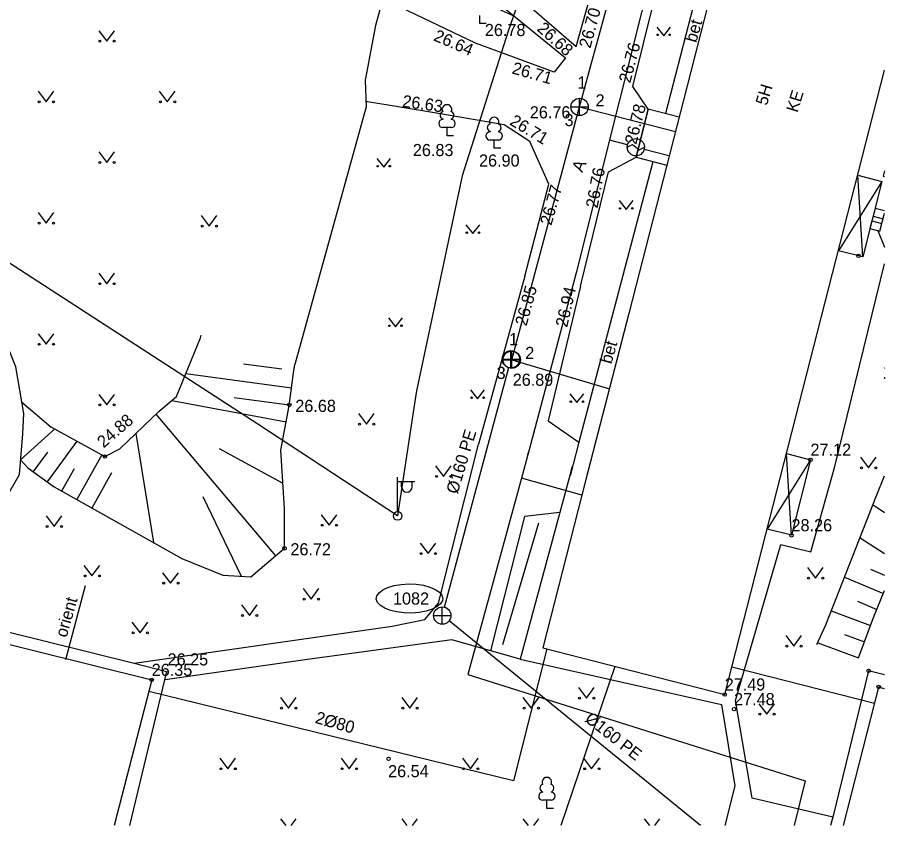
# Model space of a CAD drawing. Extents: x 714391 to 714584, y 6589993 to 6590151.
# Drawn here: x 714533.8 to 714583.9, y 6589992.7 to 6590039.4 of the extents above; entities that cross this region are included whole.
import ezdxf

# ---------------------------------------------------------------- set-up
doc = ezdxf.new("R2010")
doc.units = 0
for name, color, linetype in [('HALJASTUS', 7, 'Continuous'), ('HOONE', 7, 'Continuous'), ('HOONEDET', 7, 'Continuous'), ('KAEVU_NR', 7, 'Continuous'), ('KKAEV', 7, 'Continuous'), ('KORGUS', 7, 'Continuous'), ('KTRASS', 7, 'Continuous'), ('MPKAABEL', 7, 'Continuous'), ('POST', 7, 'Continuous'), ('PUU', 7, 'Continuous'), ('RELJEEF', 7, 'Continuous'), ('SITRASS', 7, 'Continuous'), ('TEE', 7, 'Continuous'), ('TORU NR', 7, 'Continuous'), ('TTRASS', 7, 'Continuous')]:
    doc.layers.add(name, color=color, linetype=linetype)

msp = doc.modelspace()

# ---------------------------------------------------------------- linework, layer by layer
at = {"layer": 'HALJASTUS'}
for p, q in [((714538.537, 6590038.607), (714539, 6590038)), ((714539, 6590038), (714539.446, 6590038.607)), ((714570.761, 6590038.818), (714571.166, 6590038.313)), ((714571.166, 6590038.313), (714571.561, 6590038.818)), ((714535.037, 6590035.107), (714535.5, 6590034.5)), ((714535.5, 6590034.5), (714535.946, 6590035.107)), ((714542.037, 6590035.107), (714542.5, 6590034.5)), ((714542.5, 6590034.5), (714542.946, 6590035.107)), ((714538.537, 6590031.607), (714539, 6590031)), ((714539, 6590031), (714539.446, 6590031.607)), ((714554.596, 6590031.232), (714555.001, 6590030.727)), ((714555.001, 6590030.727), (714555.396, 6590031.232)), ((714568.593, 6590028.793), (714568.998, 6590028.288)), ((714568.998, 6590028.288), (714569.393, 6590028.793)), ((714535.037, 6590028.107), (714535.5, 6590027.5)), ((714535.5, 6590027.5), (714535.946, 6590028.107)), ((714544.458, 6590027.932), (714544.921, 6590027.325)), ((714544.921, 6590027.325), (714545.367, 6590027.932)), ((714559.743, 6590027.394), (714560.148, 6590026.889)), ((714560.148, 6590026.889), (714560.543, 6590027.394)), ((714538.537, 6590024.607), (714539, 6590024)), ((714539, 6590024), (714539.446, 6590024.607)), ((714555.273, 6590022.02), (714555.678, 6590021.515)), ((714555.678, 6590021.515), (714556.073, 6590022.02)), ((714535.037, 6590021.107), (714535.5, 6590020.5)), ((714535.5, 6590020.5), (714535.946, 6590021.107)), ((714583.889, 6590019.156), (714583.92, 6590019.114)), ((714538.537, 6590017.607), (714539, 6590017)), ((714539, 6590017), (714539.446, 6590017.607)), ((714560.014, 6590017.866), (714560.419, 6590017.361)), ((714560.419, 6590017.361), (714560.814, 6590017.866)), ((714565.749, 6590017.641), (714566.154, 6590017.136)), ((714566.154, 6590017.136), (714566.549, 6590017.641)), ((714553.53, 6590016.5), (714553.993, 6590015.893)), ((714553.993, 6590015.893), (714554.439, 6590016.5)), ((714582.516, 6590013.977), (714582.979, 6590013.37)), ((714582.979, 6590013.37), (714583.425, 6590013.977)), ((714557.983, 6590013.483), (714558.446, 6590012.876)), ((714558.446, 6590012.876), (714558.892, 6590013.483)), ((714535.499, 6590010.591), (714535.962, 6590009.984)), ((714535.962, 6590009.984), (714536.408, 6590010.591)), ((714551.387, 6590010.657), (714551.85, 6590010.05)), ((714551.85, 6590010.05), (714552.296, 6590010.657)), ((714557.091, 6590009.021), (714557.554, 6590008.414)), ((714557.554, 6590008.414), (714558, 6590009.021)), ((714537.686, 6590007.732), (714538.149, 6590007.125)), ((714538.149, 6590007.125), (714538.595, 6590007.732)), ((714579.457, 6590007.611), (714579.92, 6590007.004)), ((714579.92, 6590007.004), (714580.366, 6590007.611)), ((714542.228, 6590007.311), (714542.691, 6590006.704)), ((714542.691, 6590006.704), (714543.137, 6590007.311)), ((714550.346, 6590006.393), (714550.809, 6590005.786)), ((714550.809, 6590005.786), (714551.255, 6590006.393)), ((714546.775, 6590005.451), (714547.238, 6590004.844)), ((714547.238, 6590004.844), (714547.684, 6590005.451)), ((714540.461, 6590004.453), (714540.924, 6590003.846)), ((714540.924, 6590003.846), (714541.37, 6590004.453)), ((714578.208, 6590003.68), (714578.671, 6590003.073)), ((714578.671, 6590003.073), (714579.117, 6590003.68)), ((714566.244, 6590000.679), (714566.707, 6590000.072)), ((714566.707, 6590000.072), (714567.153, 6590000.679)), ((714549.037, 6590000.107), (714549.5, 6589999.5)), ((714549.5, 6589999.5), (714549.946, 6590000.107)), ((714556.037, 6590000.107), (714556.5, 6589999.5)), ((714556.5, 6589999.5), (714556.946, 6590000.107)), ((714563.037, 6590000.107), (714563.5, 6589999.5)), ((714563.5, 6589999.5), (714563.946, 6590000.107)), ((714576.648, 6589999.748), (714577.111, 6589999.141)), ((714577.111, 6589999.141), (714577.557, 6589999.748)), ((714545.537, 6589996.607), (714546, 6589996)), ((714546, 6589996), (714546.446, 6589996.607)), ((714552.537, 6589996.607), (714553, 6589996)), ((714553, 6589996), (714553.446, 6589996.607)), ((714559.537, 6589996.607), (714560, 6589996)), ((714560, 6589996), (714560.446, 6589996.607)), ((714566.537, 6589996.607), (714567, 6589996)), ((714567, 6589996), (714567.446, 6589996.607)), ((714549.037, 6589993.107), (714549.339, 6589992.711)), ((714549.655, 6589992.711), (714549.946, 6589993.107)), ((714556.037, 6589993.107), (714556.339, 6589992.711)), ((714556.655, 6589992.711), (714556.946, 6589993.107)), ((714563.037, 6589993.107), (714563.339, 6589992.711)), ((714563.655, 6589992.711), (714563.946, 6589993.107)), ((714570.037, 6589993.107), (714570.339, 6589992.711)), ((714570.655, 6589992.711), (714570.946, 6589993.107))]:
    msp.add_line(p, q, dxfattribs=at)
msp.add_lwpolyline([(714563.928, 6590010.174), (714561.85, 6590003.147)], dxfattribs=at)
for centre, radius in [((714538.599, 6590038), 0.055), ((714539.428, 6590038), 0.055), ((714570.813, 6590038.368), 0.0428), ((714571.513, 6590038.368), 0.0452), ((714535.099, 6590034.5), 0.055), ((714535.928, 6590034.5), 0.055), ((714542.099, 6590034.5), 0.055), ((714542.928, 6590034.5), 0.055), ((714538.599, 6590031), 0.055), ((714539.428, 6590031), 0.055), ((714554.648, 6590030.782), 0.0428), ((714555.348, 6590030.782), 0.0452), ((714568.645, 6590028.344), 0.0428), ((714569.345, 6590028.344), 0.0452), ((714535.099, 6590027.5), 0.055), ((714535.928, 6590027.5), 0.055), ((714544.52, 6590027.325), 0.055), ((714545.349, 6590027.325), 0.055), ((714559.795, 6590026.944), 0.0428), ((714560.495, 6590026.944), 0.0452), ((714538.599, 6590024), 0.055), ((714539.428, 6590024), 0.055), ((714555.325, 6590021.571), 0.0428), ((714556.025, 6590021.571), 0.0452), ((714535.099, 6590020.5), 0.055), ((714535.928, 6590020.5), 0.055), ((714560.066, 6590017.417), 0.0428), ((714560.766, 6590017.417), 0.0452), ((714538.599, 6590017), 0.055), ((714539.428, 6590017), 0.055), ((714565.801, 6590017.191), 0.0428), ((714566.501, 6590017.191), 0.0452), ((714553.592, 6590015.893), 0.055), ((714554.421, 6590015.893), 0.055), ((714582.578, 6590013.37), 0.055), ((714583.407, 6590013.37), 0.055), ((714558.045, 6590012.876), 0.055), ((714558.874, 6590012.876), 0.055), ((714535.561, 6590009.984), 0.055), ((714536.39, 6590009.984), 0.055), ((714551.449, 6590010.05), 0.055), ((714552.278, 6590010.05), 0.055), ((714557.153, 6590008.414), 0.055), ((714557.982, 6590008.414), 0.055), ((714537.748, 6590007.125), 0.055), ((714538.577, 6590007.125), 0.055), ((714579.519, 6590007.004), 0.055), ((714580.348, 6590007.004), 0.055), ((714542.29, 6590006.704), 0.055), ((714543.119, 6590006.704), 0.055), ((714550.408, 6590005.786), 0.055), ((714551.237, 6590005.786), 0.055), ((714546.837, 6590004.844), 0.055), ((714547.666, 6590004.844), 0.055), ((714540.523, 6590003.846), 0.055), ((714541.352, 6590003.846), 0.055), ((714578.27, 6590003.073), 0.055), ((714579.099, 6590003.073), 0.055), ((714566.306, 6590000.072), 0.055), ((714567.135, 6590000.072), 0.055), ((714549.099, 6589999.5), 0.055), ((714549.928, 6589999.5), 0.055), ((714556.099, 6589999.5), 0.055), ((714556.928, 6589999.5), 0.055), ((714563.099, 6589999.5), 0.055), ((714563.928, 6589999.5), 0.055), ((714576.71, 6589999.141), 0.055), ((714577.539, 6589999.141), 0.055), ((714545.599, 6589996), 0.055), ((714546.428, 6589996), 0.055), ((714552.599, 6589996), 0.055), ((714553.428, 6589996), 0.055), ((714559.599, 6589996), 0.055), ((714560.428, 6589996), 0.055), ((714566.599, 6589996), 0.055), ((714567.428, 6589996), 0.055)]:
    msp.add_circle(centre, radius, dxfattribs=at)
msp.add_arc((714583.951, 6590018.549), 0.055, 123.9567, 236.0433, dxfattribs=at)
at = {"layer": 'HOONE'}
for p, q in [((714569.071, 6590032.009), (714568.027, 6590032.289)), ((714569.054, 6590031.879), (714569.354, 6590032.029)), ((714569.354, 6590032.029), (714569.754, 6590031.729)), ((714569.754, 6590031.729), (714570.054, 6590031.879)), ((714570.039, 6590031.758), (714571.46, 6590031.402))]:
    msp.add_line(p, q, dxfattribs=at)
for points in [[(714564.262, 6590078.768), (714578.616, 6590074.926), (714573.649, 6590054.703), (714566.105, 6590024.628), (714563.31, 6590014.121), (714563.349, 6590014.272), (714562.951, 6590012.774), (714559.846, 6590001.436), (714579.323, 6589995.303), (714578.688, 6589992.711)], [(714583.92, 6590060.605), (714579.267, 6590061.805), (714569.151, 6590022.283), (714566.669, 6590012.701), (714564.179, 6590002.982), (714564.176, 6590002.972), (714574.684, 6590000.28), (714583.92, 6590036.33)], [(714572.058, 6590033.612), (714570.266, 6590034.075), (714569.565, 6590031.31), (714571.34, 6590030.843)], [(714582.364, 6590030.256), (714583.754, 6590029.9), (714582.66, 6590025.541), (714581.249, 6590025.903)], [(714582.66, 6590025.541), (714582.364, 6590030.256)], [(714583.754, 6590029.9), (714581.249, 6590025.903)], [(714563.349, 6590014.272), (714563.31, 6590014.121)], [(714578.248, 6590014.189), (714579.637, 6590013.833), (714578.543, 6590009.474), (714577.132, 6590009.835)], [(714578.543, 6590009.474), (714578.248, 6590014.189)], [(714579.637, 6590013.833), (714577.132, 6590009.835)], [(714566.434, 6590011.783), (714562.951, 6590012.774)], [(714528.305, 6589992.711), (714531.142, 6590003.734), (714541.598, 6590001.124)], [(714541.598, 6590001.124), (714539.44, 6589992.711)], [(714583.92, 6590000.611), (714583.566, 6590000.701), (714581.521, 6589992.711)]]:
    msp.add_lwpolyline(points, dxfattribs=at)
msp.add_circle((714569.554, 6590031.879), 0.5, dxfattribs=at)
at = {"layer": 'HOONEDET'}
msp.add_line((714569.565, 6590031.31), (714570.266, 6590034.075), dxfattribs=at)
for points in [[(714527.976, 6589995.097), (714530.413, 6590004.606), (714540.577, 6590002.096), (714542.446, 6590001.618), (714540.308, 6589992.711)], [(714583.92, 6590001.414), (714582.992, 6590001.65), (714580.929, 6589993.204), (714580.799, 6589992.711)]]:
    msp.add_lwpolyline(points, dxfattribs=at)
at = {"layer": 'KAEVU_NR'}
msp.add_lwpolyline([(714558.405, 6590005.824), (714558.387, 6590005.71), (714558.387, 6590005.71), (714558.279, 6590005.525), (714558.279, 6590005.525), (714558.079, 6590005.355), (714558.079, 6590005.355), (714557.796, 6590005.21), (714557.796, 6590005.21), (714557.445, 6590005.097), (714557.445, 6590005.097), (714557.045, 6590005.021), (714557.045, 6590005.021), (714556.616, 6590004.986), (714556.616, 6590004.986), (714556.181, 6590004.995), (714556.181, 6590004.995), (714555.761, 6590005.046), (714555.761, 6590005.046), (714555.378, 6590005.138), (714555.378, 6590005.138), (714555.053, 6590005.265), (714555.053, 6590005.265), (714554.801, 6590005.421), (714554.801, 6590005.421), (714554.636, 6590005.597), (714554.636, 6590005.597), (714554.567, 6590005.786), (714554.567, 6590005.786), (714554.597, 6590005.976), (714554.597, 6590005.976), (714554.724, 6590006.159), (714554.724, 6590006.159), (714554.942, 6590006.324), (714554.942, 6590006.324), (714555.24, 6590006.463), (714555.24, 6590006.463), (714555.602, 6590006.57), (714555.602, 6590006.57), (714556.009, 6590006.638), (714556.009, 6590006.638), (714556.442, 6590006.664), (714556.442, 6590006.664), (714556.876, 6590006.646), (714556.876, 6590006.646), (714557.29, 6590006.587), (714557.29, 6590006.587), (714557.663, 6590006.488), (714557.663, 6590006.488), (714557.975, 6590006.354), (714557.975, 6590006.354), (714558.21, 6590006.193), (714558.21, 6590006.193), (714558.356, 6590006.014), (714558.356, 6590006.014), (714558.405, 6590005.824), (714558.405, 6590005.824)], dxfattribs=at)
at = {"layer": 'KKAEV'}
for p, q in [((714566.306, 6590033.702), (714566.306, 6590034.702)), ((714565.806, 6590034.202), (714566.806, 6590034.202)), ((714562.34, 6590019.14), (714562.34, 6590020.14)), ((714562.392, 6590019.109), (714562.392, 6590020.109)), ((714561.84, 6590019.64), (714562.84, 6590019.64)), ((714561.892, 6590019.609), (714562.892, 6590019.609)), ((714558.378, 6590004.342), (714558.378, 6590005.342)), ((714557.878, 6590004.842), (714558.878, 6590004.842))]:
    msp.add_line(p, q, dxfattribs=at)
for centre in [(714566.306, 6590034.202), (714562.34, 6590019.64), (714562.392, 6590019.609), (714558.378, 6590004.842)]:
    msp.add_circle(centre, 0.5, dxfattribs=at)
at = {"layer": 'KORGUS'}
for centre in [(714582.411, 6590025.605), (714549.547, 6590017.002), (714538.897, 6590014.023), (714579.637, 6590013.833), (714578.543, 6590009.474), (714549.264, 6590008.722), (714582.992, 6590001.65), (714541.598, 6590001.124), (714574.684, 6590000.28), (714583.571, 6590000.719), (714575.227, 6589999.433), (714555.277, 6589996.567)]:
    msp.add_circle(centre, 0.1, dxfattribs=at)
at = {"layer": 'KTRASS'}
for p, q in [((714566.306, 6590034.202), (714571.457, 6590053.19)), ((714562.392, 6590019.609), (714566.306, 6590034.202)), ((714566.306, 6590034.202), (714571.84, 6590032.789)), ((714562.392, 6590019.609), (714568.025, 6590017.935))]:
    msp.add_line(p, q, dxfattribs=at)
for points in [[(714558.507, 6590005.325), (714562.211, 6590019.157)], [(714573.285, 6589992.711), (714558.766, 6590004.526)]]:
    msp.add_lwpolyline(points, dxfattribs=at)
at = {"layer": 'MPKAABEL'}
for points in [[(714565.296, 6590047.518), (714562.179, 6590038.578), (714559.533, 6590030.225), (714556.889, 6590017.808), (714556.781, 6590017.088), (714556.359, 6590014.294), (714555.801, 6590010.589), (714547.733, 6590015.896), (714531.176, 6590026.61), (714500.538, 6590019.577)], [(714583.501, 6590027.101), (714583.92, 6590026.1)]]:
    msp.add_lwpolyline(points, dxfattribs=at)
at = {"layer": 'POST'}
for p, q in [((714583.373, 6590028.343), (714583.064, 6590027.189)), ((714583.92, 6590028.197), (714583.373, 6590028.343)), ((714583.641, 6590027.035), (714583.92, 6590028.079)), ((714583.184, 6590027.635), (714583.76, 6590027.481)), ((714583.254, 6590027.897), (714583.83, 6590027.743)), ((714583.064, 6590027.189), (714583.641, 6590027.035)), ((714555.801, 6590010.839), (714555.801, 6590012.839)), ((714555.801, 6590012.589), (714556.801, 6590012.589)), ((714556.028, 6590012.268), (714556.028, 6590012.589)), ((714556.64, 6590012.268), (714556.64, 6590012.589))]:
    msp.add_line(p, q, dxfattribs=at)
msp.add_circle((714555.801, 6590010.589), 0.25, dxfattribs=at)
msp.add_arc((714556.334, 6590012.268), 0.306, 180, 0, dxfattribs=at)
at = {"layer": 'PUU'}
for p, q in [((714560.539, 6590039.015), (714560.539, 6590039.49)), ((714560.919, 6590039.015), (714560.539, 6590039.015)), ((714558.41, 6590033.516), (714558.41, 6590033.486)), ((714558.89, 6590033.516), (714558.89, 6590033.486)), ((714558.89, 6590033.011), (714558.41, 6590033.011)), ((714558.65, 6590032.536), (714558.65, 6590033.011)), ((714559.03, 6590032.536), (714558.65, 6590032.536)), ((714561.135, 6590032.799), (714561.135, 6590032.769)), ((714561.615, 6590032.799), (714561.615, 6590032.769)), ((714561.615, 6590032.294), (714561.135, 6590032.294)), ((714561.375, 6590031.819), (714561.375, 6590032.294)), ((714561.755, 6590031.819), (714561.375, 6590031.819)), ((714564.658, 6589994.175), (714564.178, 6589994.175)), ((714564.418, 6589993.7), (714564.418, 6589994.175)), ((714564.798, 6589993.7), (714564.418, 6589993.7))]:
    msp.add_line(p, q, dxfattribs=at)
for centre, radius, start, end in [((714558.65, 6590034.056), 0.277, 332.5799, 207.4201), ((714558.412, 6590033.249), 0.237, 90, 270), ((714558.46, 6590033.724), 0.212, 105.2441, 257.079), ((714558.887, 6590033.249), 0.237, 270, 90), ((714558.84, 6590033.724), 0.212, 282.921, 74.7559), ((714561.375, 6590033.339), 0.277, 332.5799, 207.4201), ((714561.185, 6590033.007), 0.212, 105.2441, 257.079), ((714561.565, 6590033.007), 0.212, 282.921, 74.7559), ((714561.137, 6590032.531), 0.237, 90, 270), ((714561.612, 6590032.531), 0.237, 270, 90), ((714564.418, 6589995.22), 0.277, 332.5799, 207.4201), ((714564.248, 6589994.873), 0.233, 109.0217, 253.1415), ((714564.588, 6589994.873), 0.233, 286.8508, 70.9859), ((714564.181, 6589994.412), 0.238, 90.0016, 269.3953), ((714564.655, 6589994.412), 0.238, 270.6047, 89.9984)]:
    msp.add_arc(centre, radius, start, end, dxfattribs=at)
at = {"layer": 'RELJEEF'}
for points in [[(714562.558, 6590039.424), (714560.262, 6590040.479), (714558.242, 6590041.236), (714555.943, 6590041.488), (714554.821, 6590040.031), (714554.512, 6590038.91), (714553.923, 6590035.744), (714553.979, 6590034.203), (714549.861, 6590019.341)], [(714534.101, 6590017.166), (714535.781, 6590015.731), (714538.897, 6590014.023), (714539.751, 6590014.475), (714542.028, 6590016.64), (714543.038, 6590017.493), (714544.414, 6590020.871), (714544.452, 6590021.028)], [(714534.03, 6590013.833), (714534.442, 6590013.377), (714535.963, 6590012.263), (714543.34, 6590008.142), (714545.701, 6590007.171), (714547.329, 6590007.084), (714549.264, 6590008.722), (714549.264, 6590011.02), (714549.058, 6590014.381), (714549.538, 6590016.953), (714549.795, 6590018.85), (714549.861, 6590019.341)], [(714546.89, 6590019.379), (714549.118, 6590019.079)], [(714543.578, 6590018.818), (714549.679, 6590017.994)], [(714546.367, 6590017.432), (714549.545, 6590017.003)], [(714542.755, 6590017.254), (714549.364, 6590016.019)], [(714541.838, 6590016.46), (714548.754, 6590008.29)], [(714535.998, 6590015.612), (714534.03, 6590013.833)], [(714537.281, 6590014.909), (714535.56, 6590012.558)], [(714540.675, 6590015.354), (714541.709, 6590009.053)], [(714545.486, 6590014.485), (714549.174, 6590012.481)], [(714535.575, 6590014.271), (714534.753, 6590013.149)], [(714538.719, 6590014.12), (714537.273, 6590011.531)], [(714537.121, 6590013.31), (714536.4, 6590012.019)], [(714539.281, 6590013.075), (714538.146, 6590011.043)], [(714580.012, 6590003.167), (714580.52, 6590004.309), (714583.438, 6590011.708), (714583.92, 6590012.913)], [(714544.551, 6590011.707), (714546.764, 6590007.114)], [(714583.248, 6590011.225), (714583.92, 6590010.794)], [(714582.5, 6590009.329), (714583.92, 6590008.419)], [(714583.106, 6590007.516), (714583.92, 6590007.176)], [(714581.605, 6590007.06), (714583.854, 6590006.119)], [(714582.405, 6590002.392), (714583.272, 6590004.728), (714583.92, 6590006.279)], [(714582.353, 6590005.663), (714583.468, 6590005.197)], [(714580.835, 6590005.108), (714583.101, 6590004.267)], [(714581.607, 6590003.754), (714582.753, 6590003.329)], [(714580.055, 6590003.264), (714582.405, 6590002.392)]]:
    msp.add_lwpolyline(points, dxfattribs=at)
at = {"layer": 'SITRASS'}
msp.add_line((714536.636, 6590002.309), (714537.77, 6590006.584), dxfattribs=at)
msp.add_lwpolyline([(714568.333, 6590001.907), (714565.216, 6589992.711)], dxfattribs=at)
at = {"layer": 'TEE'}
for p, q in [((714575.561, 6590050.401), (714571.262, 6590033.816)), ((714563.14, 6590024.436), (714560.476, 6590014.732))]:
    msp.add_line(p, q, dxfattribs=at)
for points in [[(714523.83, 6590060.323), (714524.838, 6590059.346), (714527.207, 6590057.322), (714530.612, 6590055.143), (714533.466, 6590053.803), (714539.862, 6590051.373), (714544.939, 6590049.949), (714549.327, 6590048.405), (714554.662, 6590046.175), (714555.973, 6590045.43), (714557.565, 6590044.068), (714560.558, 6590042.157), (714562.991, 6590040.414), (714566.112, 6590037.695), (714570.003, 6590051.519), (714571.762, 6590062.449)], [(714530.594, 6590004.671), (714529.575, 6590005.355), (714533.957, 6590012.977), (714534.157, 6590015.322), (714534.216, 6590016.497), (714533.749, 6590019.201), (714531.843, 6590023.902), (714529.246, 6590029.211), (714527.989, 6590032.696), (714528.19, 6590034.745), (714530.462, 6590043.175), (714532.838, 6590052.177), (714538.719, 6590050.416), (714545.918, 6590048.286), (714551.944, 6590046.002), (714557.184, 6590043.351), (714560.131, 6590041.46), (714562.296, 6590039.644), (714565.486, 6590037.034), (714564.832, 6590036.22), (714560.292, 6590037.889), (714555.09, 6590040.381)], [(714570.266, 6590034.075), (714569.384, 6590035.393), (714573.093, 6590050.376), (714574.585, 6590050.689)], [(714563.14, 6590024.436), (714564.533, 6590029.748), (714563.424, 6590032.21), (714561.942, 6590033.166), (714558.167, 6590033.821), (714553.968, 6590034.517)], [(714570.544, 6590031.044), (714566.254, 6590014.851), (714565.753, 6590012.916), (714565.868, 6590013.421), (714562.875, 6590002.32), (714574.49, 6589999.706), (714575.278, 6589995.019), (714574.698, 6589992.711)], [(714566.355, 6590023.857), (714567.966, 6590030.449), (714569.565, 6590031.31)], [(714583.92, 6590030.513), (714583.839, 6590030.215), (714583.92, 6590030.195)], [(714575.316, 6589999.931), (714577.926, 6590008.933), (714579.657, 6590008.519), (714581.036, 6590013.442), (714583.92, 6590025.141)], [(714566.355, 6590023.857), (714564.497, 6590016.082), (714566.254, 6590014.851)], [(714540.577, 6590002.096), (714555.48, 6590004.225), (714557.374, 6590004.62), (714558.154, 6590005.561), (714560.476, 6590014.732)], [(714565.161, 6590010.798), (714563.123, 6590010.552), (714561.168, 6590002.803)], [(714562.875, 6590002.32), (714558.922, 6590003.44), (714550.46, 6590002.28), (714542.369, 6590001.127)], [(714580.929, 6589993.204), (714576.272, 6589994.305), (714575.316, 6589999.931)]]:
    msp.add_lwpolyline(points, dxfattribs=at)
at = {"layer": 'TTRASS'}
for points in [[(714564.418, 6590002.91), (714562.493, 6589995.291), (714541.427, 6590000.461)], [(714583.329, 6589999.77), (714575.087, 6590001.854)]]:
    msp.add_lwpolyline(points, dxfattribs=at)

# ---------------------------------------------------------------- texts
at = {"layer": 'HOONE'}
for s, p in [('5H', (714577.118, 6590034.244)), ('KE', (714578.887, 6590033.843))]:
    msp.add_text(s, height=0.7, rotation=73.0726, dxfattribs=at).set_placement(p)
at = {"layer": 'HOONEDET'}
for p in [(714573.041, 6590037.878), (714568.144, 6590019.327)]:
    msp.add_text('bet', height=0.7, rotation=74.1412, dxfattribs=at).set_placement(p)
at = {"layer": 'KAEVU_NR'}
msp.add_text('1082', height=0.7, dxfattribs=at).set_placement((714555.531, 6590005.474))
at = {"layer": 'KORGUS'}
for s, rotation, p in [('26.70', 74.9315, (714566.928, 6590037.554)), ('26.68', 317.8755, (714563.801, 6590038.657)), ('26.64', 336.7099, (714557.826, 6590038.06)), ('26.76', 75.2218, (714569.229, 6590035.547)), ('26.71', 344.1025, (714562.355, 6590036.147)), ('26.63', 352.0992, (714556.038, 6590034.211)), ('26.78', 75.9638, (714569.574, 6590031.998)), ('26.71', 328.9729, (714562.217, 6590033.21)), ('26.76', 79.0278, (714567.336, 6590028.327)), ('26.77', 74.1128, (714564.674, 6590027.325)), ('26.85', 74.71, (714563.24, 6590021.518)), ('26.94', 77.125, (714565.586, 6590021.445)), ('24.88', 40.7277, (714538.823, 6590014.483))]:
    msp.add_text(s, height=0.7, rotation=rotation, dxfattribs=at).set_placement(p)
for s, p in [('26.78', (714560.837, 6590038.297)), ('26.76', (714563.431, 6590033.544)), ('26.83', (714556.679, 6590031.366)), ('26.90', (714560.499, 6590030.762)), ('26.89', (714562.443, 6590018.106)), ('26.68', (714549.891, 6590016.597)), ('27.12', (714579.637, 6590014.066)), ('28.26', (714578.543, 6590009.707)), ('26.72', (714549.607, 6590008.317)), ('26.25', (714542.516, 6590001.96)), ('26.35', (714541.598, 6590001.357)), ('27.49', (714574.684, 6590000.513)), ('27.48', (714575.227, 6589999.666)), ('26.54', (714555.249, 6589995.507))]:
    msp.add_text(s, height=0.7, dxfattribs=at).set_placement(p)
at = {"layer": 'KTRASS'}
for rotation, p in [(73.128, (714559.254, 6590011.814)), (321.8247, (714566.56, 6589998.775))]:
    msp.add_text('%%c160 PE', height=0.7, rotation=rotation, dxfattribs=at).set_placement(p)
at = {"layer": 'SITRASS'}
msp.add_text('orient', height=0.7, rotation=73.9626, dxfattribs=at).set_placement((714536.679, 6590003.534))
at = {"layer": 'TEE'}
msp.add_text('A', height=0.7, rotation=67.1355, dxfattribs=at).set_placement((714566.464, 6590030.386))
at = {"layer": 'TORU NR'}
for s, p in [('1', (714566.184, 6590035.267)), ('2', (714567.229, 6590034.232)), ('3', (714565.438, 6590033.098)), ('1', (714562.234, 6590020.45)), ('2', (714563.169, 6590019.654)), ('3', (714561.517, 6590018.499))]:
    msp.add_text(s, height=0.7, dxfattribs=at).set_placement(p)
at = {"layer": 'TTRASS'}
msp.add_text('2%%c80', height=0.7, rotation=344.0465, dxfattribs=at).set_placement((714550.992, 6589998.652))

doc.saveas('drawing.dxf')
